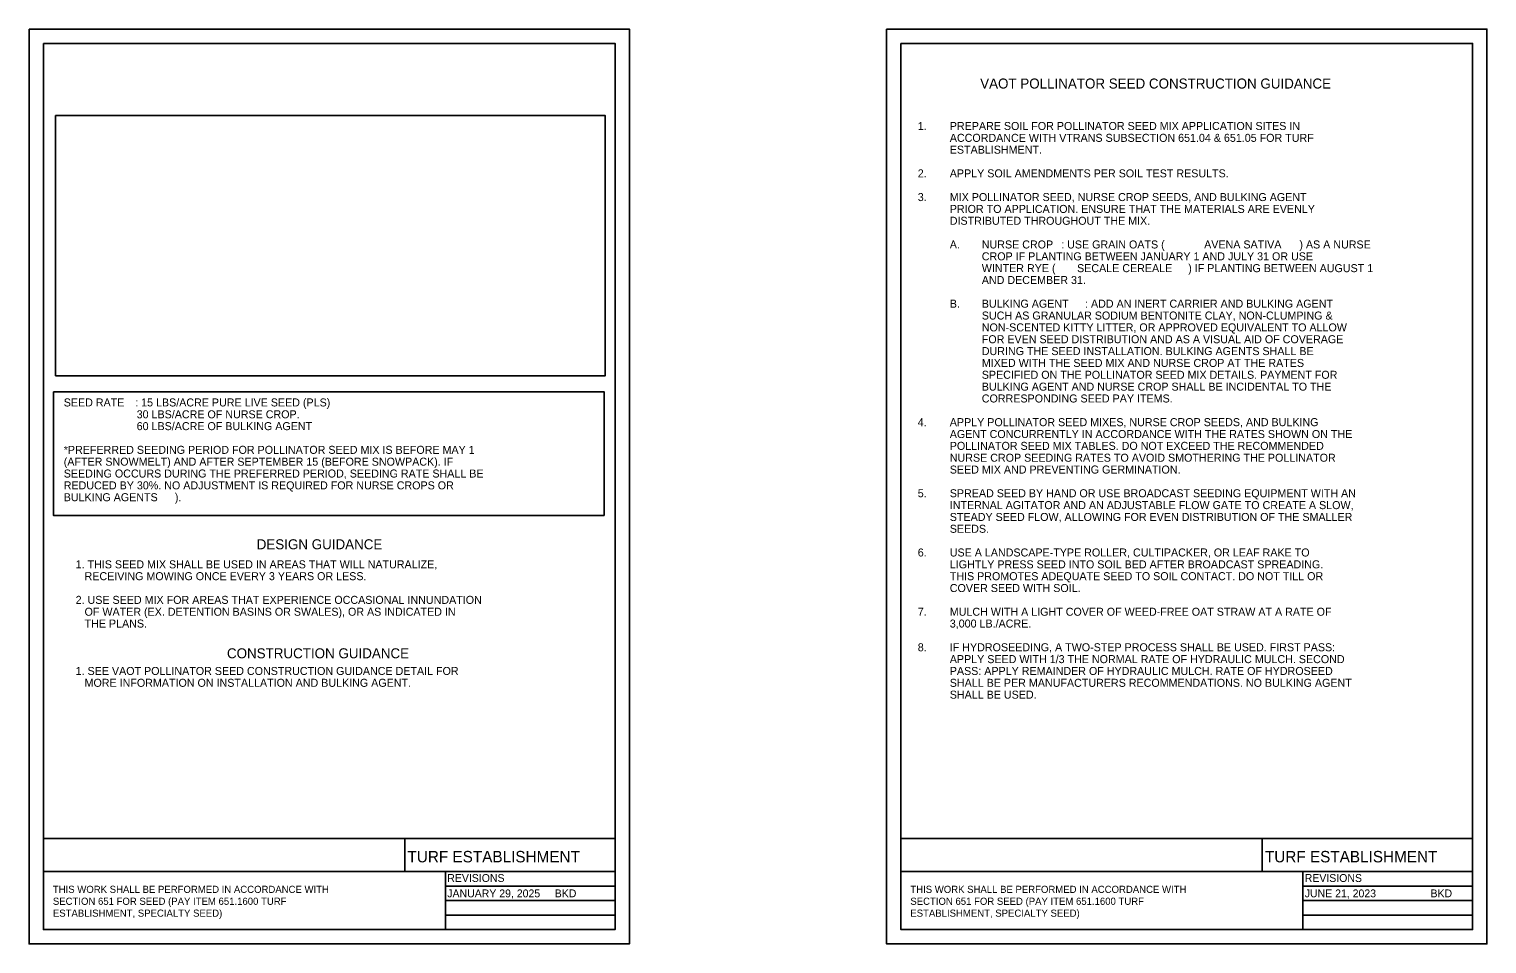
# Model space of a CAD drawing. Extents: x 900 to 2010, y -766 to -287.
# Drawn here: x 1500 to 2010, y -766 to -446 of the extents above; entities that cross this region are included whole.
import ezdxf

# ---------------------------------------------------------------- set-up
doc = ezdxf.new("R2010")
doc.units = 0
for name, color, linetype in [('NBC1', 7, 'Continuous'), ('NBL1', 7, 'Continuous'), ('NBL1_T', 7, 'Continuous'), ('NBLNC1', 7, 'Continuous')]:
    doc.layers.add(name, color=color, linetype=linetype)

msp = doc.modelspace()

# ---------------------------------------------------------------- linework, layer by layer
at = {"layer": 'NBC1'}
for points in [[(1500, -445.85), (1710, -445.85), (1710, -765.85), (1500, -765.85)], [(1800, -445.85), (2010, -445.85), (2010, -765.85), (1800, -765.85)]]:
    msp.add_lwpolyline(points, close=True, dxfattribs=at)
at = {"layer": 'NBL1'}
for p, q in [((1631.4, -729.01), (1631.4, -740.54)), ((1931.4, -729.01), (1931.4, -740.54)), ((1705, -740.54), (1505, -740.54)), ((2005, -740.54), (1805, -740.54))]:
    msp.add_line(p, q, dxfattribs=at)
for points in [[(1505, -450.85), (1705, -450.85), (1705, -760.85), (1505, -760.85)], [(1805, -450.85), (2005, -450.85), (2005, -760.85), (1805, -760.85)]]:
    msp.add_lwpolyline(points, close=True, dxfattribs=at)
for points in [[(1705, -729.01), (1505, -729.01)], [(2005, -729.01), (1805, -729.01)]]:
    msp.add_lwpolyline(points, dxfattribs=at)
at = {"layer": 'NBL1_T'}
for points in [[(1509.25, -567.13), (1701.53, -567.13), (1701.53, -476.11), (1509.25, -476.11)], [(1508.48, -572.69), (1701.15, -572.69), (1701.15, -615.95), (1508.48, -615.95)]]:
    msp.add_lwpolyline(points, close=True, dxfattribs=at)
at = {"layer": 'NBLNC1'}
for points in [[(1645.64, -740.54), (1705, -740.54), (1705, -745.62), (1645.64, -745.62)], [(1945.64, -740.54), (2005, -740.54), (2005, -745.62), (1945.64, -745.62)], [(1645.64, -745.62), (1705, -745.62), (1705, -750.69), (1645.64, -750.69)], [(1945.64, -745.62), (2005, -745.62), (2005, -750.69), (1945.64, -750.69)], [(1645.64, -750.69), (1705, -750.69), (1705, -755.77), (1645.64, -755.77)], [(1945.64, -750.69), (2005, -750.69), (2005, -755.77), (1945.64, -755.77)], [(1645.64, -755.77), (1705, -755.77), (1705, -760.85), (1645.64, -760.85)], [(1945.64, -755.77), (2005, -755.77), (2005, -760.85), (1945.64, -760.85)]]:
    msp.add_lwpolyline(points, close=True, dxfattribs=at)

# ---------------------------------------------------------------- texts
at = {"layer": 'NBL1_T'}
for s, height, p in [('TURF ESTABLISHMENT', 4, (1632.36, -737.34)), ('TURF ESTABLISHMENT', 4, (1932.36, -737.34)), ('THIS WORK SHALL BE PERFORMED IN ACCORDANCE WITH ', 2.5, (1508.3, -748.03)), ('SECTION 651 FOR SEED (PAY ITEM 651.1600 TURF ', 2.5, (1508.3, -752.2)), ('THIS WORK SHALL BE PERFORMED IN ACCORDANCE WITH ', 2.5, (1808.3, -748.03)), ('SECTION 651 FOR SEED (PAY ITEM 651.1600 TURF ', 2.5, (1808.3, -752.2)), ('ESTABLISHMENT, SPECIALTY SEED)', 2.5, (1508.3, -756.36)), ('ESTABLISHMENT, SPECIALTY SEED)', 2.5, (1808.3, -756.36))]:
    msp.add_text(s, height=height, dxfattribs=at).set_placement(p)
at = {"layer": 'NBLNC1'}
for s, height, p in [('VAOT POLLINATOR SEED CONSTRUCTION GUIDANCE', 3.5, (1832.74, -466.62)), ('1. ', 2.8, (1810.9, -481.12)), ('PREPARE SOIL FOR POLLINATOR SEED MIX APPLICATION SITES IN ', 2.8, (1822.1, -481.12)), ('ACCORDANCE WITH VTRANS SUBSECTION 651.04 & 651.05 FOR TURF ', 2.8, (1822.1, -485.27)), ('ESTABLISHMENT.', 2.8, (1822.1, -489.41)), ('2.', 2.8, (1810.9, -497.7)), ('APPLY SOIL AMENDMENTS PER SOIL TEST RESULTS.', 2.8, (1822.1, -497.7)), ('3.', 2.8, (1810.9, -505.99)), ('MIX POLLINATOR SEED, NURSE CROP SEEDS, AND BULKING AGENT ', 2.8, (1822.1, -505.99)), ('PRIOR TO APPLICATION. ENSURE THAT THE MATERIALS ARE EVENLY ', 2.8, (1822.1, -510.14)), ('DISTRIBUTED THROUGHOUT THE MIX.', 2.8, (1822.1, -514.28)), ('A.', 2.8, (1822.1, -522.57)), ('NURSE CROP', 2.8, (1833.3, -522.57)), (': USE GRAIN OATS (', 2.8, (1861.08, -522.57)), ('AVENA SATIVA', 2.8, (1911.09, -522.57)), (') AS A NURSE ', 2.8, (1944.42, -522.57)), ('CROP IF PLANTING BETWEEN JANUARY 1 AND JULY 31 OR USE ', 2.8, (1833.3, -526.72)), ('WINTER RYE (', 2.8, (1833.3, -530.86)), ('SECALE CEREALE', 2.8, (1866.64, -530.86)), (') IF PLANTING BETWEEN AUGUST 1 ', 2.8, (1905.53, -530.86)), ('AND DECEMBER 31.', 2.8, (1833.3, -535.01)), ('B.', 2.8, (1822.1, -543.29)), ('BULKING AGENT', 2.8, (1833.3, -543.29)), (': ADD AN INERT CARRIER AND BULKING AGENT ', 2.8, (1869.42, -543.29)), ('SUCH AS GRANULAR SODIUM BENTONITE CLAY, NON-CLUMPING &', 2.8, (1833.3, -547.44)), ('NON-SCENTED KITTY LITTER, OR APPROVED EQUIVALENT TO ALLOW ', 2.8, (1833.3, -551.58)), ('FOR EVEN SEED DISTRIBUTION AND AS A VISUAL AID OF COVERAGE ', 2.8, (1833.3, -555.73)), ('DURING THE SEED INSTALLATION. BULKING AGENTS SHALL BE ', 2.8, (1833.3, -559.87)), ('SPECIFIED ON THE POLLINATOR SEED MIX DETAILS. PAYMENT FOR ', 2.8, (1833.3, -568.16)), ('MIXED WITH THE SEED MIX AND NURSE CROP AT THE RATES ', 2.8, (1833.3, -564.02)), ('BULKING AGENT AND NURSE CROP SHALL BE INCIDENTAL TO THE ', 2.8, (1833.3, -572.31)), ('SEED RATE', 2.8, (1512.1, -577.84)), (': 15 LBS/ACRE PURE LIVE SEED (PLS) ', 2.8, (1537.1, -577.84)), ('CORRESPONDING SEED PAY ITEMS.', 2.8, (1833.3, -576.45)), ('   30 LBS/ACRE OF NURSE CROP. ', 2.8, (1534.5, -581.99)), ('   60 LBS/ACRE OF BULKING AGENT ', 2.8, (1534.5, -586.13)), ('4.', 2.8, (1810.9, -584.74)), ('APPLY POLLINATOR SEED MIXES, NURSE CROP SEEDS, AND BULKING ', 2.8, (1822.1, -584.74)), ('AGENT CONCURRENTLY IN ACCORDANCE WITH THE RATES SHOWN ON THE ', 2.8, (1822.1, -588.89)), ('*PREFERRED SEEDING PERIOD FOR POLLINATOR SEED MIX IS BEFORE MAY 1 ', 2.8, (1512.1, -594.42)), ('POLLINATOR SEED MIX TABLES. DO NOT EXCEED THE RECOMMENDED ', 2.8, (1822.1, -593.03)), ('(AFTER SNOWMELT) AND AFTER SEPTEMBER 15 (BEFORE SNOWPACK). IF ', 2.8, (1512.1, -598.56)), ('NURSE CROP SEEDING RATES TO AVOID SMOTHERING THE POLLINATOR ', 2.8, (1822.1, -597.18)), ('SEEDING OCCURS DURING THE PREFERRED PERIOD, SEEDING RATE SHALL BE ', 2.8, (1512.1, -602.71)), ('SEED MIX AND PREVENTING GERMINATION.', 2.8, (1822.1, -601.32)), ('REDUCED BY 30%. NO ADJUSTMENT IS REQUIRED FOR NURSE CROPS OR ', 2.8, (1512.1, -606.85)), ('5.', 2.8, (1810.9, -609.61)), ('SPREAD SEED BY HAND OR USE BROADCAST SEEDING EQUIPMENT WITH AN ', 2.8, (1822.1, -609.61)), ('BULKING AGENTS', 2.8, (1512.1, -611)), (').', 2.8, (1550.99, -611)), ('INTERNAL AGITATOR AND AN ADJUSTABLE FLOW GATE TO CREATE A SLOW, ', 2.8, (1822.1, -613.76)), ('STEADY SEED FLOW, ALLOWING FOR EVEN DISTRIBUTION OF THE SMALLER ', 2.8, (1822.1, -617.9)), ('SEEDS.', 2.8, (1822.1, -622.04)), ('DESIGN GUIDANCE', 3.5, (1579.62, -627.81)), ('1. THIS SEED MIX SHALL BE USED IN AREAS THAT WILL NATURALIZE, ', 2.8, (1516.27, -634.48)), ('6.', 2.8, (1810.9, -630.33)), ('USE A LANDSCAPE-TYPE ROLLER, CULTIPACKER, OR LEAF RAKE TO ', 2.8, (1822.1, -630.33)), ('LIGHTLY PRESS SEED INTO SOIL BED AFTER BROADCAST SPREADING. ', 2.8, (1822.1, -634.48)), ('   RECEIVING MOWING ONCE EVERY 3 YEARS OR LESS.', 2.8, (1516.27, -638.62)), ('THIS PROMOTES ADEQUATE SEED TO SOIL CONTACT. DO NOT TILL OR ', 2.8, (1822.1, -638.62)), ('COVER SEED WITH SOIL.', 2.8, (1822.1, -642.77)), ('2. USE SEED MIX FOR AREAS THAT EXPERIENCE OCCASIONAL INNUNDATION ', 2.8, (1516.27, -646.91)), ('   THE PLANS.', 2.8, (1516.27, -655.2)), ('   OF WATER (EX. DETENTION BASINS OR SWALES), OR AS INDICATED IN ', 2.8, (1516.27, -651.06)), ('7.', 2.8, (1810.9, -651.06)), ('3,000 LB./ACRE.', 2.8, (1822.1, -655.2)), ('MULCH WITH A LIGHT COVER OF WEED-FREE OAT STRAW AT A RATE OF ', 2.8, (1822.1, -651.06)), ('CONSTRUCTION GUIDANCE', 3.5, (1569.21, -665.95)), ('8.', 2.8, (1810.9, -663.49)), ('IF HYDROSEEDING, A TWO-STEP PROCESS SHALL BE USED. FIRST PASS: ', 2.8, (1822.1, -663.49)), ('APPLY SEED WITH 1/3 THE NORMAL RATE OF HYDRAULIC MULCH. SECOND ', 2.8, (1822.1, -667.64)), ('1. SEE VAOT POLLINATOR SEED CONSTRUCTION GUIDANCE DETAIL FOR ', 2.8, (1516.27, -671.78)), ('   MORE INFORMATION ON INSTALLATION AND BULKING AGENT.', 2.8, (1516.27, -675.92)), ('SHALL BE PER MANUFACTURERS RECOMMENDATIONS. NO BULKING AGENT ', 2.8, (1822.1, -675.93)), ('PASS: APPLY REMAINDER OF HYDRAULIC MULCH. RATE OF HYDROSEED ', 2.8, (1822.1, -671.78)), ('SHALL BE USED.', 2.8, (1822.1, -680.07)), ('REVISIONS', 2.75, (1646.29, -744.19)), ('REVISIONS', 2.75, (1946.29, -744.19)), ('JANUARY 29, 2025     BKD', 2.75, (1646.29, -749.57)), ('JUNE 21, 2023   ', 2.75, (1946.29, -749.57)), ('BKD', 2.75, (1990.29, -749.57))]:
    msp.add_text(s, height=height, dxfattribs=at).set_placement(p)

doc.saveas('drawing.dxf')
